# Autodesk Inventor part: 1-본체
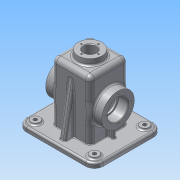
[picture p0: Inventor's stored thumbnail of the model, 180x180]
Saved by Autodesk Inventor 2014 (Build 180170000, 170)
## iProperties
Created: 2015-12
Part Number: 1-본체
Material: 알루미늄 6061
Document SubType Name: Modeling
Designer: Administrator
Density: 2.71 g/cm^3
Appearance: 알루미늄 - 평지
Author: Administrator
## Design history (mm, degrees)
sketch "스케치1"
  geometry: L1 (-50, -52.5)-(50, -52.5); L2 (60, -42.5)-(60, 42.5); L3 (50, 52.5)-(-50, 52.5); L4 (-60, 42.5)-(-60, -42.5); L5 (-60, -52.5)-(60, 52.5); L6 (60, -52.5)-(-60, 52.5); A1 r 10 centre (-50, 42.5) between (-50, 52.5) and (-60, 42.5); A2 r 10 centre (50, 42.5) between (60, 42.5) and (50, 52.5); A3 r 10 centre (-50, -42.5) between (-60, -42.5) and (-50, -52.5); A4 r 10 centre (50, -42.5) between (50, -52.5) and (60, -42.5); 1 further point
  constraints: 12 end point, 8 point on circle, 8 point on line, 8 tangent, 4 centre point, 3 equal radius, 2 midpoint, 2 parallel, 1 horizontal, 1 perpendicular
  dimensions: "d0" = 120 distance of L5.end L6.end; "d1" = 105 distance of L6.start L5.end; "d2" = 10 radius of A1
extrude "돌출1" new body sketch "스케치1" distance "d3" = 2; taper "d4" = 0 deg
sketch "스케치2"
  geometry: L1 (50, 52.5)-(-50, 52.5) reference; L2 (-60, 42.5)-(-60, -42.5) reference; L3 (-50, -52.5)-(50, -52.5) reference; L4 (60, -42.5)-(60, 42.5) reference; L5 (-50, 57.5)-(50, 57.5); L6 (65, 42.5)-(65, -42.5); L7 (50, -57.5)-(-50, -57.5); L8 (-65, -42.5)-(-65, 42.5); A1 r 10 centre (-50, 42.5) between (-50, 52.5) and (-60, 42.5) reference; A2 r 10 centre (-50, -42.5) between (-60, -42.5) and (-50, -52.5) reference; A3 r 10 centre (50, -42.5) between (50, -52.5) and (60, -42.5) reference; A4 r 10 centre (50, 42.5) between (60, 42.5) and (50, 52.5) reference; A5 r 15 centre (50, 42.5) between (65, 42.5) and (50, 57.5); A6 r 15 centre (50, -42.5) between (50, -57.5) and (65, -42.5); A7 r 15 centre (-50, -42.5) between (-65, -42.5) and (-50, -57.5); A8 r 15 centre (-50, 42.5) between (-50, 57.5) and (-65, 42.5); 1 further point
  constraints: 8 end point, 8 point on circle, 4 centre point, 7 other
  dimensions: "d5" = 5 distance between parallel lines of L1 L5
extrude "돌출2" join sketch "스케치2" distance "d6" = 8; taper "d7" = 0 deg
sketch "스케치3"
  geometry: L1 (-32.5, -32.5)-(32.5, -32.5); L2 (32.5, -32.5)-(32.5, 32.5); L3 (32.5, 32.5)-(-32.5, 32.5); L4 (-32.5, 32.5)-(-32.5, -32.5); L5 (-32.5, -32.5)-(32.5, 32.5); L6 (32.5, -32.5)-(-32.5, 32.5); 1 further point
  constraints: 12 end point, 2 midpoint, 2 parallel, 2 perpendicular, 1 horizontal
  dimensions: "d8" = 65 distance of L2.end L3.end
extrude "돌출3" join sketch "스케치3" distance "d9" = 100; taper "d10" = 0 deg
feature "쉘1" dims "d11" = 10, "d12" = 5
sketch "스케치5"
  geometry: L1 (10, 75)-(10, -10) reference; C1 r 27.5 at (-45, 32.5); 2 further points
  constraints: 1 centre point, 1 horizontal alignment, 1 midpoint
  dimensions: "d15" = 55 diameter of C1; "d16" = 55 distance from line of C1.centre L1
extrude "돌출4" join sketch "스케치5" distance "d17" = 15; taper "d18" = 0 deg
sketch "스케치6"
  geometry: C1 r 27.5 at (0, 0) reference; 2 further points
  constraints: 1 vertical alignment
  dimensions: "d19" = 21 distance of C1.centre point (0, 21)
hole "구멍1" sketch "스케치6" at (0, 21) diameter "d20" = 3.242; stored, may be unused: countersink angle "d24" = 90 deg, drill point angle "d26" = 118 deg; dims "d21" = 8, "d22" = 4, "d23" = 2, "d25" = 10
hole "구멍2" diameter "d32" = 30; stored, may be unused: countersink angle "d36" = 90 deg, drill point angle "d38" = 0 deg; dims "d30" = 10, "d31" = 10, "d33" = 8, "d34" = 35, "d35" = 17, "d37" = 35
node "작업 평면1"
sketch "스케치7"
  geometry: C1 r 20 at (0, 0); 1 further point
  constraints: 1 centre point, 1 coincident
  dimensions: "d40" = 40 diameter of C1
extrude "돌출5" join sketch "스케치7" stored distance "d41" = 15; taper "d42" = 5 deg
sketch "스케치8"
  geometry: C1 r 20 at (0, 0) reference; 1 further point
  constraints: 1 vertical alignment
  dimensions: "d43" = 14.5 distance of C1.centre point (0, 14.5)
hole "구멍3" sketch "스케치8" at (0, 14.5) diameter "d44" = 2.459; stored, may be unused: countersink angle "d48" = 90 deg, drill point angle "d50" = 118 deg; dims "d45" = 7, "d46" = 35, "d47" = 17, "d49" = 9
hole "구멍4" diameter "d56" = 21; stored, may be unused: countersink angle "d60" = 90 deg, drill point angle "d62" = 0 deg; dims "d54" = 10, "d55" = 10, "d57" = 7, "d58" = 35, "d59" = 17, "d61" = 9
sketch "스케치9"
  geometry: L1 (32.5, 10)-(32.5, 110) reference; L2 (42.5, 10)-(-42.5, 10) reference; L3 (57.5, 10)-(42.5, 10) reference; L4 (47.5, 10)-(32.5, 95.069); L5 (57.5, 2)-(57.5, 10) reference; 1 further point
  constraints: 2 end point, 2 point on line
  dimensions: "d63" = 10 distance of L3.start L4.start; "d64" = 10 deg angle of L5 L4
extrude "돌출6" join sketch "스케치9" stored distance "d65" = 10; taper "d66" = 0 deg
sketch "스케치10"
  geometry: L1 (32.5, 10)-(32.5, 110) reference; L2 (50, 10)-(-50, 10) reference; L3 (47.5, 27.5)-(32.5, 27.5) reference; L4 (27.5, 0)-(27.5, 105) reference; L5 (42.5, 10)-(42.5, 31); L6 (42.5, 31)-(31, 31); L7 (31, 31)-(31, 7); L8 (31, 7)-(42.5, 8); L9 (42.5, 8)-(42.5, 10); 2 further points
  constraints: 10 end point, 2 parallel, 2 perpendicular, 2 point on line
  dimensions: "d130" = 15 distance between parallel lines of L5 L4; "d131" = 4.96974 deg angle of L2 L8; "d132" = 21 distance between parallel lines of L2 L6; "d133" = 1.5 distance between parallel lines of L1 L7; "d134" = 1.34276 distance from line of L2.start L8; "d135" = 10 distance from line of point (42.5, 27.5) L1
extrude "돌출7" join sketch "스케치10" stored distance "d68" = 6; taper "d69" = 0 deg
sketch "스케치11"
  geometry: C1 r 7.5 at (-50, 42.5); C2 r 7.5 at (50, 42.5); C3 r 7.5 at (50, -42.5); C4 r 7.5 at (-50, -42.5); A1 r 15 centre (-50, 42.5) between (-50, 57.5) and (-65, 42.5) reference; A2 r 15 centre (-50, -42.5) between (-65, -42.5) and (-50, -57.5) reference; A3 r 15 centre (50, -42.5) between (50, -57.5) and (65, -42.5) reference; A4 r 15 centre (50, 42.5) between (65, 42.5) and (50, 57.5) reference; 1 further point
  constraints: 4 centre point, 4 coincident
  dimensions: "d70" = 15 diameter of C1; "d71" = 15 diameter of C2; "d72" = 15 diameter of C3; "d73" = 15 diameter of C4
extrude "돌출8" join sketch "스케치11" distance "d74" = 3; taper "d75" = 0 deg
hole "구멍5" diameter "d78" = 6; stored, may be unused: countersink angle "d82" = 90 deg, drill point angle "d84" = 0 deg; dims "d76" = 10, "d77" = 10, "d79" = 7, "d80" = 35, "d81" = 17, "d83" = 9
hole "구멍6" diameter "d87" = 6; stored, may be unused: countersink angle "d91" = 90 deg, drill point angle "d93" = 0 deg; dims "d85" = 10, "d86" = 10, "d88" = 7, "d89" = 35, "d90" = 17, "d92" = 9
hole "구멍7" diameter "d96" = 6; stored, may be unused: countersink angle "d100" = 90 deg, drill point angle "d102" = 0 deg; dims "d94" = 10, "d95" = 10, "d97" = 7, "d98" = 35, "d99" = 17, "d101" = 9
hole "구멍8" diameter "d105" = 6; stored, may be unused: countersink angle "d109" = 90 deg, drill point angle "d111" = 0 deg; dims "d103" = 10, "d104" = 10, "d106" = 7, "d107" = 35, "d108" = 17, "d110" = 9
node "작업 평면2"
sketch "스케치15"
  geometry: L1 (10, 52.5)-(10, 12.5) reference; L2 (-100, 65)-(0, 65) reference; 2 further points
  constraints: 1 other
  dimensions: "d119" = 26 distance from line of L1 point (-16, 32.5); "d120" = 32.5 distance from line of point (-16, 32.5) L2
extrude "돌출9" join sketch "스케치15" stored distance "d121" = 3; taper "d122" = 0 deg
chamfer "모따기1" distance "d123" = 1; stored, may be unused: second distance "d124" = 2, angle "d125" = 45 deg
fillet "모깎기1" dims "d126" = 0.3
fillet "모깎기4" dims "d129" = 3
fillet "모깎기5" dims "d136" = 3
fillet "모깎기6" dims "d137" = 3
fillet "모깎기7" dims "d138" = 8
fillet "모깎기8" dims "d139" = 8
fillet "모깎기9" dims "d140" = 1
fillet "모깎기10" dims "d141" = 3
fillet "모깎기11" dims "d142" = 3
fillet "모깎기12" dims "d143" = 3
fillet "모깎기13" dims "d144" = 3
fillet "모깎기14" dims "d145" = 3
node "솔리드1"
pattern_circular "원형 패턴1" dims angle "d28" = 360 deg
mirror "대칭1"
pattern_circular "원형 패턴2" dims angle "d52" = 360 deg
mirror "대칭2"
mirror "대칭3"
other parameters: "d118" = 0.5
